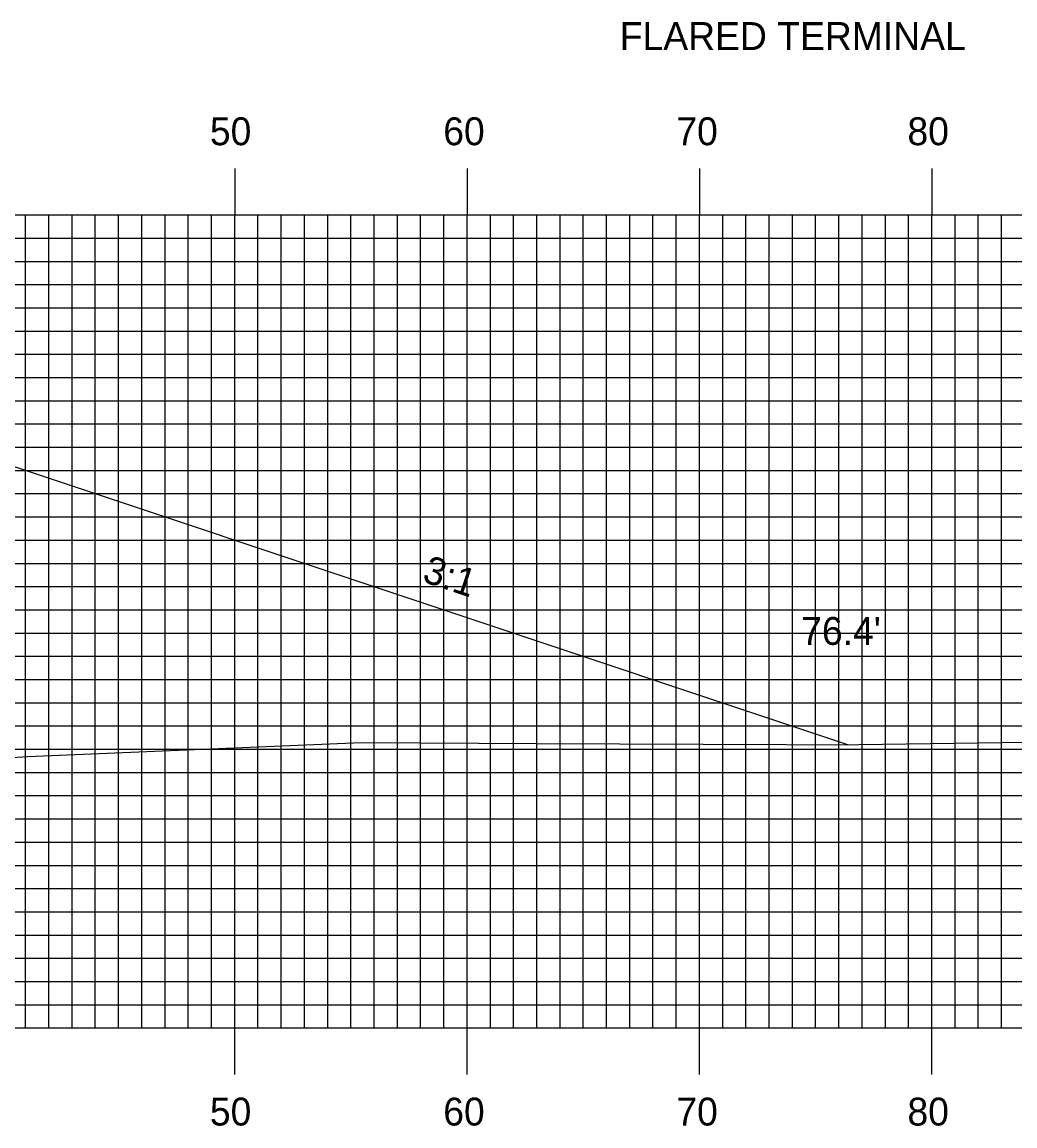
# Model space of a CAD drawing. Extents: x 1788943 to 1789287, y 442591 to 442811.
# Drawn here: x 1789150 to 1789192.73, y 442659.45 to 442706.97 of the extents above; entities that cross this region are included whole.
import ezdxf

# ---------------------------------------------------------------- set-up
doc = ezdxf.new("R2010")
doc.units = 0
for name, color, linetype in [('ANNOTATION', 7, 'Continuous'), ('D_Roadway_Centerline', 7, 'Continuous'), ('D_Roadway_SlopeLines', 7, 'Continuous'), ('D_Text_Standard', 7, 'Continuous'), ('H_V ANNOTATION', 7, 'Continuous'), ('MAJOR', 7, 'Continuous'), ('MINOR', 7, 'Continuous'), ('S_Roadway_Centerline', 7, 'Continuous')]:
    doc.layers.add(name, color=color, linetype=linetype)

msp = doc.modelspace()

# ---------------------------------------------------------------- linework, layer by layer
at = {"layer": 'D_Roadway_Centerline'}
msp.add_lwpolyline([(1789035.212, 442674.103), (1789075.728, 442687.608), (1789079.49, 442688.548), (1789087.728, 442690.608), (1789097.156, 442690.985), (1789109.156, 442691.249), (1789121.156, 442691.513), (1789137.57, 442690.857), (1789145.201, 442688.949), (1789149.57, 442687.857), (1789185.572, 442675.856)], dxfattribs=at)
at = {"layer": 'D_Roadway_SlopeLines'}
msp.add_lwpolyline([(1789137.57, 442690.857), (1789149.57, 442687.857), (1789185.572, 442675.856)], dxfattribs=at)
at = {"layer": 'MAJOR'}
for p, q in [((1789159.156, 442700.669), (1789159.156, 442698.665)), ((1789169.156, 442700.669), (1789169.156, 442698.665)), ((1789179.156, 442700.669), (1789179.156, 442698.665)), ((1789189.156, 442700.669), (1789189.156, 442698.665)), ((1788969.156, 442698.665), (1789249.156, 442698.665)), ((1788969.156, 442698.665), (1789249.156, 442698.665)), ((1789159.156, 442663.665), (1789159.156, 442698.665)), ((1789169.156, 442663.665), (1789169.156, 442698.665)), ((1789179.156, 442663.665), (1789179.156, 442698.665)), ((1789189.156, 442663.665), (1789189.156, 442698.665)), ((1788969.156, 442693.665), (1789249.156, 442693.665)), ((1788969.156, 442688.665), (1789249.156, 442688.665)), ((1788969.156, 442683.665), (1789249.156, 442683.665)), ((1788969.156, 442678.665), (1789249.156, 442678.665)), ((1788969.156, 442673.665), (1789249.156, 442673.665)), ((1788969.156, 442668.665), (1789249.156, 442668.665)), ((1788969.156, 442663.665), (1789249.156, 442663.665)), ((1788969.156, 442663.665), (1789249.156, 442663.665)), ((1789159.156, 442661.661), (1789159.156, 442663.665)), ((1789169.156, 442661.661), (1789169.156, 442663.665)), ((1789179.156, 442661.661), (1789179.156, 442663.665)), ((1789189.156, 442661.661), (1789189.156, 442663.665))]:
    msp.add_line(p, q, dxfattribs=at)
at = {"layer": 'MINOR'}
for p, q in [((1789150.156, 442663.665), (1789150.156, 442698.665)), ((1789151.156, 442663.665), (1789151.156, 442698.665)), ((1789152.156, 442663.665), (1789152.156, 442698.665)), ((1789153.156, 442663.665), (1789153.156, 442698.665)), ((1789154.156, 442663.665), (1789154.156, 442698.665)), ((1789155.156, 442663.665), (1789155.156, 442698.665)), ((1789156.156, 442663.665), (1789156.156, 442698.665)), ((1789157.156, 442663.665), (1789157.156, 442698.665)), ((1789158.156, 442663.665), (1789158.156, 442698.665)), ((1789160.156, 442663.665), (1789160.156, 442698.665)), ((1789161.156, 442663.665), (1789161.156, 442698.665)), ((1789162.156, 442663.665), (1789162.156, 442698.665)), ((1789163.156, 442663.665), (1789163.156, 442698.665)), ((1789164.156, 442663.665), (1789164.156, 442698.665)), ((1789165.156, 442663.665), (1789165.156, 442698.665)), ((1789166.156, 442663.665), (1789166.156, 442698.665)), ((1789167.156, 442663.665), (1789167.156, 442698.665)), ((1789168.156, 442663.665), (1789168.156, 442698.665)), ((1789170.156, 442663.665), (1789170.156, 442698.665)), ((1789171.156, 442663.665), (1789171.156, 442698.665)), ((1789172.156, 442663.665), (1789172.156, 442698.665)), ((1789173.156, 442663.665), (1789173.156, 442698.665)), ((1789174.156, 442663.665), (1789174.156, 442698.665)), ((1789175.156, 442663.665), (1789175.156, 442698.665)), ((1789176.156, 442663.665), (1789176.156, 442698.665)), ((1789177.156, 442663.665), (1789177.156, 442698.665)), ((1789178.156, 442663.665), (1789178.156, 442698.665)), ((1789180.156, 442663.665), (1789180.156, 442698.665)), ((1789181.156, 442663.665), (1789181.156, 442698.665)), ((1789182.156, 442663.665), (1789182.156, 442698.665)), ((1789183.156, 442663.665), (1789183.156, 442698.665)), ((1789184.156, 442663.665), (1789184.156, 442698.665)), ((1789185.156, 442663.665), (1789185.156, 442698.665)), ((1789186.156, 442663.665), (1789186.156, 442698.665)), ((1789187.156, 442663.665), (1789187.156, 442698.665)), ((1789188.156, 442663.665), (1789188.156, 442698.665)), ((1789190.156, 442663.665), (1789190.156, 442698.665)), ((1789191.156, 442663.665), (1789191.156, 442698.665)), ((1789192.156, 442663.665), (1789192.156, 442698.665)), ((1788969.156, 442697.665), (1789249.156, 442697.665)), ((1788969.156, 442696.665), (1789249.156, 442696.665)), ((1788969.156, 442695.665), (1789249.156, 442695.665)), ((1788969.156, 442694.665), (1789249.156, 442694.665)), ((1788969.156, 442692.665), (1789249.156, 442692.665)), ((1788969.156, 442691.665), (1789249.156, 442691.665)), ((1788969.156, 442690.665), (1789249.156, 442690.665)), ((1788969.156, 442689.665), (1789249.156, 442689.665)), ((1788969.156, 442687.665), (1789249.156, 442687.665)), ((1788969.156, 442686.665), (1789249.156, 442686.665)), ((1788969.156, 442685.665), (1789249.156, 442685.665)), ((1788969.156, 442684.665), (1789249.156, 442684.665)), ((1788969.156, 442682.665), (1789249.156, 442682.665)), ((1788969.156, 442681.665), (1789249.156, 442681.665)), ((1788969.156, 442680.665), (1789249.156, 442680.665)), ((1788969.156, 442679.665), (1789249.156, 442679.665)), ((1788969.156, 442677.665), (1789249.156, 442677.665)), ((1788969.156, 442676.665), (1789249.156, 442676.665)), ((1788969.156, 442675.665), (1789249.156, 442675.665)), ((1788969.156, 442674.665), (1789249.156, 442674.665)), ((1788969.156, 442672.665), (1789249.156, 442672.665)), ((1788969.156, 442671.665), (1789249.156, 442671.665)), ((1788969.156, 442670.665), (1789249.156, 442670.665)), ((1788969.156, 442669.665), (1789249.156, 442669.665)), ((1788969.156, 442667.665), (1789249.156, 442667.665)), ((1788969.156, 442666.665), (1789249.156, 442666.665)), ((1788969.156, 442665.665), (1789249.156, 442665.665)), ((1788969.156, 442664.665), (1789249.156, 442664.665))]:
    msp.add_line(p, q, dxfattribs=at)
at = {"layer": 'S_Roadway_Centerline'}
msp.add_lwpolyline([(1789063.262, 442674.604), (1789072.58, 442674.527), (1789075.066, 442674.537), (1789080.562, 442674.661), (1789099.205, 442675.236), (1789109.147, 442674.937), (1789111.106, 442674.915), (1789114.589, 442674.896), (1789124.001, 442675.043), (1789128.979, 442675.008), (1789141.801, 442675.1), (1789145.761, 442675.163), (1789147.464, 442675.16), (1789150.23, 442675.344), (1789164.616, 442675.959), (1789172.157, 442675.916), (1789182.892, 442675.861), (1789184.991, 442675.847), (1789200.307, 442676.07)], dxfattribs=at)

# ---------------------------------------------------------------- texts
at = {"layer": 'ANNOTATION'}
msp.add_text('3:1', height=1.2, rotation=341.5652, dxfattribs=at).set_placement((1789167.175, 442682.897))
at = {"layer": 'D_Text_Standard'}
for s, p in [('FLARED TERMINAL', (1789175.726, 442705.765)), ("76.4'", (1789183.534, 442680.155))]:
    msp.add_text(s, height=1.2, dxfattribs=at).set_placement(p)
at = {"layer": 'H_V ANNOTATION'}
for s, p in [('50', (1789158.086, 442701.665)), ('60', (1789168.129, 442701.665)), ('70', (1789178.161, 442701.665)), ('80', (1789188.107, 442701.665)), ('50', (1789158.086, 442659.465)), ('60', (1789168.129, 442659.465)), ('70', (1789178.161, 442659.465)), ('80', (1789188.107, 442659.465))]:
    msp.add_text(s, height=1.2, dxfattribs=at).set_placement(p)

doc.saveas('drawing.dxf')
